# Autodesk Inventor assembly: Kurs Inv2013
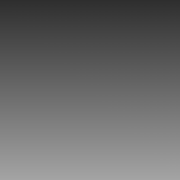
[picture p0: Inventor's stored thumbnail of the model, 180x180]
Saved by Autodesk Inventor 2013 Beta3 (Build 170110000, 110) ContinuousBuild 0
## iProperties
Created: 2010-03
Part Number: Kurs Inv2013
Document SubType Name: Assembly
Designer: Johan Wedeen
Manufacturer: Standard
Standards Organization: Custom
Author: Johan Wedeen
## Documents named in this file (1)
- C:\Program Files\Autodesk\Inventor 2013\Templates\InventorKurs\Kurs Inv2013.iam
